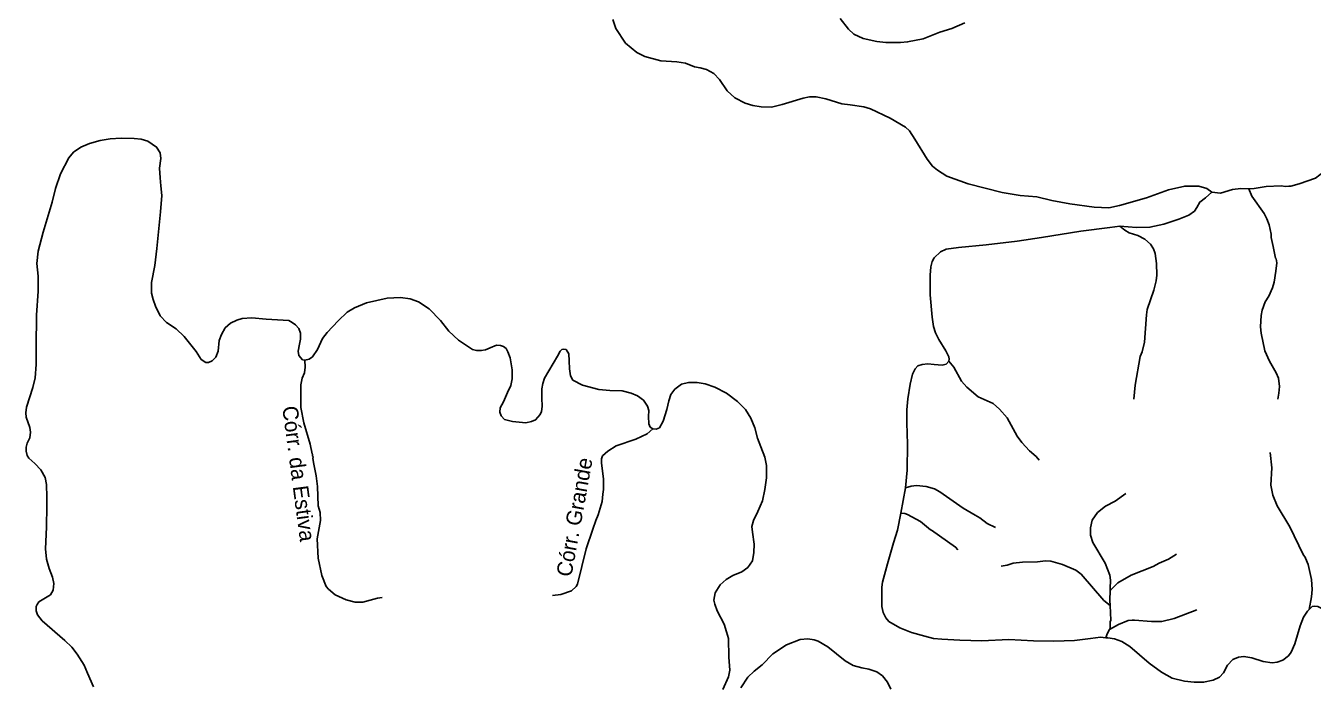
# Model space of a CAD drawing. Extents: x 396 to 422.2, y 7649.8 to 7677.6.
# Drawn here: x 402.44 to 409.11, y 7655.45 to 7658.86 of the extents above; entities that cross this region are included whole.
import ezdxf
from ezdxf.enums import TextEntityAlignment as Align

# ---------------------------------------------------------------- set-up
doc = ezdxf.new("R2010")
doc.units = 0
doc.header["$LTSCALE"] = 0.032
doc.layers.add('2', color=7, linetype='Continuous', lineweight=25)
doc.layers.add('7', color=7, linetype='Continuous', lineweight=25)
doc.layers.add('61', color=7, linetype='Continuous')

msp = doc.modelspace()

# ---------------------------------------------------------------- linework, layer by layer
at = {"layer": '2'}
for points in [[(408.5913, 7658.0004), (408.5664, 7658.0192), (408.5251, 7658.0301), (408.4514, 7658.031), (408.3678, 7658.0124), (408.2537, 7657.9701), (408.1131, 7657.9298), (408.0571, 7657.9189), (407.9814, 7657.9219), (407.8555, 7657.9396), (407.7621, 7657.9573), (407.6834, 7657.975), (407.5979, 7657.9819), (407.5035, 7657.9986), (407.3285, 7658.0428), (407.2164, 7658.0822), (407.1692, 7658.1136), (407.1426, 7658.1343), (407.1151, 7658.1707), (407.0512, 7658.2749), (407.0226, 7658.3182), (407.002, 7658.3368), (406.9224, 7658.384), (406.8211, 7658.4322), (406.7867, 7658.4421), (406.7159, 7658.4529), (406.6726, 7658.4578), (406.589, 7658.4834), (406.5398, 7658.4932), (406.5045, 7658.4932), (406.471, 7658.4873), (406.3629, 7658.4539), (406.3078, 7658.4411), (406.2537, 7658.443), (406.2104, 7658.4489), (406.1711, 7658.4607), (406.117, 7658.4883), (406.0767, 7658.5256), (406.0384, 7658.5846), (406.0089, 7658.6151), (405.9705, 7658.6358), (405.9371, 7658.6446), (405.9076, 7658.6495), (405.8614, 7658.6692), (405.8161, 7658.6761), (405.7326, 7658.68), (405.65, 7658.7036), (405.6087, 7658.7233), (405.5507, 7658.7724), (405.5005, 7658.8491), (405.4838, 7658.8954)], [(402.7899, 7655.435), (402.7584, 7655.506), (402.741, 7655.5479), (402.7061, 7655.605), (402.677, 7655.6399), (402.642, 7655.6748), (402.5233, 7655.7772), (402.5, 7655.8075), (402.4931, 7655.8296), (402.4931, 7655.8517), (402.4977, 7655.861), (402.507, 7655.875), (402.5326, 7655.8913), (402.5664, 7655.9122), (402.5815, 7655.9367), (402.585, 7655.9704), (402.578, 7656.003), (402.5606, 7656.0484), (402.5466, 7656.0961), (402.5408, 7656.1497), (402.5466, 7656.2626), (402.5478, 7656.3732), (402.5478, 7656.4186), (402.5466, 7656.4837), (402.5385, 7656.5198), (402.5175, 7656.5594), (402.4861, 7656.5931), (402.4547, 7656.6211), (402.4453, 7656.635), (402.4407, 7656.656), (402.4407, 7656.6769), (402.4453, 7656.6979), (402.4605, 7656.7258), (402.464, 7656.7561), (402.4593, 7656.7794), (402.4407, 7656.8329), (402.4384, 7656.8562), (402.4419, 7656.8841), (402.4744, 7656.9865), (402.4872, 7657.0366), (402.4919, 7657.1064), (402.4919, 7657.1972), (402.4942, 7657.3613), (402.5035, 7657.487), (402.5035, 7657.5639), (402.4966, 7657.6302), (402.5035, 7657.6931), (402.5291, 7657.7931), (402.5757, 7657.948), (402.5932, 7658.019), (402.6188, 7658.0946), (402.6618, 7658.1772), (402.6863, 7658.2075), (402.7247, 7658.2331), (402.7689, 7658.2517), (402.8248, 7658.268), (402.8772, 7658.2762), (402.933, 7658.2797), (403.0005, 7658.2785), (403.0366, 7658.275), (403.0727, 7658.2634), (403.1169, 7658.2331), (403.1356, 7658.2029), (403.139, 7658.1749), (403.1332, 7658.1237), (403.1356, 7658.0748), (403.139, 7658.0329), (403.1437, 7657.9817), (403.1379, 7657.8979), (403.1181, 7657.7073), (403.1088, 7657.6188), (403.0917, 7657.5318), (403.0917, 7657.4759)], [(408.1152, 7657.823), (408.2006, 7657.8167), (408.2705, 7657.8177), (408.3432, 7657.8344), (408.4209, 7657.859), (408.472, 7657.8796), (408.5015, 7657.9012), (408.5143, 7657.9209), (408.5291, 7657.9484), (408.5586, 7657.9711), (408.5913, 7658.0004)], [(407.2275, 7657.1227), (407.2291, 7657.1333), (407.2282, 7657.1451), (407.2124, 7657.1766), (407.176, 7657.2355), (407.1583, 7657.27), (407.1485, 7657.3034), (407.1416, 7657.3516), (407.1308, 7657.4676), (407.1308, 7657.5699), (407.1338, 7657.6122), (407.1406, 7657.6397), (407.1515, 7657.6584), (407.1849, 7657.6898), (407.2144, 7657.7036), (407.2773, 7657.7134), (407.4209, 7657.7272), (407.5812, 7657.7459), (407.708, 7657.7646), (407.9125, 7657.797), (408.062, 7657.8167), (408.1152, 7657.823)], [(403.0917, 7657.4759), (403.0995, 7657.4433), (403.1119, 7657.4092), (403.1367, 7657.3579), (403.1693, 7657.3238), (403.219, 7657.2911)], [(403.8864, 7657.1288), (403.9084, 7657.1343), (403.9255, 7657.1452), (403.9519, 7657.184), (403.9774, 7657.2405), (404.002, 7657.2729), (404.06, 7657.3329), (404.1062, 7657.3781), (404.1436, 7657.3998), (404.2055, 7657.4253), (404.3137, 7657.4509), (404.3825, 7657.4538), (404.4336, 7657.446), (404.4759, 7657.4312), (404.532, 7657.3948), (404.59, 7657.3349), (404.6342, 7657.2798), (404.6844, 7657.2316), (404.7561, 7657.1834), (404.7778, 7657.1785), (404.8014, 7657.1785), (404.824, 7657.1825), (404.8476, 7657.1923), (404.88, 7657.2061), (404.9017, 7657.2041), (404.9174, 7657.1992), (404.9312, 7657.1884), (404.939, 7657.1726), (404.9508, 7657.1412), (404.9626, 7657.0782), (404.9617, 7657.031), (404.9548, 7656.9966), (404.9381, 7656.9612), (404.9164, 7656.913), (404.8997, 7656.8816), (404.8987, 7656.8589), (404.9046, 7656.8393), (404.9223, 7656.8206), (404.9636, 7656.8108), (405.0325, 7656.8029), (405.0629, 7656.8098), (405.0836, 7656.8196), (405.1072, 7656.8471), (405.1141, 7656.8629), (405.117, 7656.8884), (405.1151, 7656.9327), (405.116, 7656.9799), (405.121, 7657.0074), (405.1298, 7657.035), (405.1967, 7657.15), (405.2104, 7657.1756), (405.2203, 7657.1834), (405.2291, 7657.1854), (405.2419, 7657.1834), (405.2557, 7657.1618), (405.2576, 7657.1244), (405.2586, 7657.0831), (405.2645, 7657.0477), (405.2773, 7657.0251), (405.3274, 7656.9986), (405.412, 7656.9769), (405.469, 7656.972), (405.533, 7656.9691), (405.5802, 7656.9573), (405.6126, 7656.9445), (405.6431, 7656.9209), (405.6637, 7656.8894), (405.6716, 7656.8678), (405.6696, 7656.8363), (405.6716, 7656.798), (405.6775, 7656.7813), (405.6909, 7656.772)], [(403.219, 7657.2911), (403.261, 7657.2508), (403.3231, 7657.1731), (403.3479, 7657.1328), (403.3728, 7657.1172), (403.3867, 7657.1172), (403.4054, 7657.125), (403.4255, 7657.1436), (403.4364, 7657.1747), (403.4411, 7657.2306), (403.4535, 7657.2616), (403.4737, 7657.2958), (403.5001, 7657.3206), (403.5342, 7657.3362), (403.5606, 7657.3455), (403.6119, 7657.3486), (403.6849, 7657.3408), (403.8029, 7657.3346), (403.8215, 7657.3238), (403.8386, 7657.3113), (403.8557, 7657.2927), (403.8634, 7657.2679), (403.8634, 7657.2383), (403.8588, 7657.212), (403.8525, 7657.1747), (403.8557, 7657.1529), (403.8743, 7657.1312), (403.8864, 7657.1288)], [(407.0023, 7656.4674), (407.0118, 7656.5581), (407.0128, 7656.6938), (407.0089, 7656.8029), (407.0099, 7656.8707), (407.0148, 7656.9288), (407.0266, 7657.0045), (407.0384, 7657.0566), (407.0521, 7657.0841), (407.0669, 7657.0989), (407.0885, 7657.1067), (407.118, 7657.1097), (407.1515, 7657.1058), (407.1928, 7657.1028), (407.2134, 7657.1077), (407.2275, 7657.1227)], [(405.6909, 7656.772), (405.709, 7656.7714), (405.7257, 7656.7773), (405.7453, 7656.8117), (405.765, 7656.8727), (405.7739, 7656.917), (405.7857, 7656.9514), (405.8063, 7656.9779), (405.8407, 7657.0035), (405.8771, 7657.0133), (405.9214, 7657.0133), (405.9627, 7657.0055), (406.0128, 7656.9878), (406.0747, 7656.9583), (406.1308, 7656.915), (406.1731, 7656.8727), (406.1996, 7656.8275), (406.2203, 7656.7783), (406.235, 7656.7242), (406.2527, 7656.68), (406.2734, 7656.6249), (406.2822, 7656.5826), (406.2822, 7656.5187), (406.2734, 7656.4578), (406.2606, 7656.3997), (406.237, 7656.3437), (406.2144, 7656.2975), (406.2045, 7656.267), (406.2085, 7656.2375), (406.2183, 7656.1746), (406.2163, 7656.1313), (406.2095, 7656.089), (406.1839, 7656.0536), (406.1534, 7656.031), (406.1062, 7656.0123), (406.0718, 7655.9917), (406.0413, 7655.9641), (406.0158, 7655.9228), (406.0089, 7655.8835), (406.0128, 7655.8629), (406.0256, 7655.8285), (406.061, 7655.7606), (406.0747, 7655.7203), (406.0836, 7655.6859), (406.0865, 7655.5895), (406.0905, 7655.5217), (406.0836, 7655.4872), (406.0541, 7655.4214)], [(408.0422, 7655.6897), (408.0148, 7655.6918), (407.9627, 7655.6859), (407.8791, 7655.6751), (407.7719, 7655.6711), (407.6667, 7655.6731), (407.5389, 7655.681), (407.3983, 7655.6741), (407.2842, 7655.676), (407.1908, 7655.6819), (407.1485, 7655.6859), (407.1033, 7655.6977), (407.0335, 7655.7164), (406.9735, 7655.74), (406.9165, 7655.7744), (406.8997, 7655.7931), (406.886, 7655.8196), (406.8801, 7655.8511), (406.8801, 7655.9514), (406.884, 7655.9769), (406.9086, 7656.0733), (406.9401, 7656.1815), (406.9617, 7656.2473), (406.9776, 7656.3348), (407.0023, 7656.4674)], [(409.6179, 7655.872), (409.5999, 7655.8432), (409.5497, 7655.7852), (409.4976, 7655.7301), (409.4602, 7655.7065), (409.4327, 7655.6957), (409.4032, 7655.6878), (409.3668, 7655.6878), (409.3314, 7655.6967), (409.2931, 7655.7164), (409.2626, 7655.737), (409.1869, 7655.8176), (409.1594, 7655.8432), (409.1417, 7655.8511), (409.123, 7655.853), (409.1131, 7655.8511), (409.0962, 7655.8359)], [(409.0962, 7655.8359), (409.0876, 7655.8265), (409.0669, 7655.796), (409.0502, 7655.7508), (409.0227, 7655.6583), (409.004, 7655.6151), (408.9892, 7655.5954), (408.9597, 7655.5738), (408.9312, 7655.562), (408.9047, 7655.559), (408.8575, 7655.5659), (408.7985, 7655.5856), (408.7582, 7655.5925), (408.7306, 7655.5885), (408.7002, 7655.5757), (408.6736, 7655.5472), (408.653, 7655.5069), (408.6323, 7655.4853), (408.5979, 7655.4695), (408.5487, 7655.4587), (408.4996, 7655.4587), (408.4504, 7655.4636), (408.3865, 7655.4804), (408.3304, 7655.5108), (408.2665, 7655.5571), (408.1662, 7655.6436), (408.1249, 7655.6692), (408.0866, 7655.6829), (408.0531, 7655.6888), (408.0422, 7655.6897)], [(406.1485, 7655.4302), (406.1849, 7655.4853), (406.2183, 7655.5167), (406.2586, 7655.5482), (406.3137, 7655.6062), (406.3845, 7655.6534), (406.4553, 7655.68), (406.4966, 7655.6839), (406.528, 7655.679), (406.5487, 7655.6721), (406.5988, 7655.6426), (406.6903, 7655.5689), (406.7306, 7655.5462), (406.7758, 7655.5335), (406.8132, 7655.5256), (406.8535, 7655.5128), (406.883, 7655.4922), (406.9086, 7655.4597), (406.9263, 7655.4233)]]:
    msp.add_lwpolyline(points, dxfattribs=at)
at = {"layer": '7'}
for points in [[(407.3106, 7658.877), (407.243, 7658.8488), (407.1802, 7658.8285), (407.0936, 7658.7954), (407.0138, 7658.7787), (406.9763, 7658.7751), (406.9006, 7658.7761), (406.8543, 7658.7806), (406.7837, 7658.7958), (406.7342, 7658.8187), (406.707, 7658.8457), (406.6631, 7658.8994)], [(409.5566, 7658.3901), (409.5118, 7658.3631), (409.4656, 7658.3248), (409.4286, 7658.3001), (409.384, 7658.2791), (409.2962, 7658.2244), (409.1978, 7658.1248), (409.1288, 7658.0721), (409.0448, 7658.0422), (409.0021, 7658.0315), (408.9914, 7658.0306), (408.9738, 7658.029), (408.9513, 7658.0319), (408.8741, 7658.0295), (408.8109, 7658.0191), (408.7832, 7658.0178)], [(408.5913, 7658.0004), (408.6371, 7657.9953), (408.6989, 7658.0135), (408.7424, 7658.0189), (408.7832, 7658.0178)], [(408.7832, 7658.0178), (408.7999, 7657.9794), (408.8626, 7657.8896), (408.8774, 7657.8615), (408.8885, 7657.8301), (408.8998, 7657.7823), (408.9, 7657.7652), (408.9098, 7657.7174), (408.9222, 7657.6574), (408.9255, 7657.6549), (408.9286, 7657.6328), (408.9246, 7657.5898), (408.9149, 7657.5324), (408.906, 7657.5032), (408.8873, 7657.4612), (408.8687, 7657.4319), (408.8525, 7657.3878), (408.8473, 7657.3608), (408.8441, 7657.3006), (408.8473, 7657.2692), (408.8669, 7657.1773), (408.8911, 7657.1242), (408.9256, 7657.0634), (408.9374, 7657.0347), (408.9421, 7656.9913), (408.9397, 7656.9582), (408.9335, 7656.9259)], [(408.1152, 7657.823), (408.1403, 7657.8025), (408.1636, 7657.7884), (408.2071, 7657.7742), (408.2448, 7657.7561), (408.2728, 7657.7299), (408.289, 7657.7065), (408.2985, 7657.681), (408.3049, 7657.6299), (408.3066, 7657.569), (408.3032, 7657.5399), (408.2905, 7657.4909), (408.2568, 7657.392), (408.2524, 7657.364), (408.2426, 7657.2225), (408.23, 7657.1722), (408.2205, 7657.1471), (408.1946, 7656.9988), (408.187, 7656.9259)], [(404.288, 7655.8979), (404.2636, 7655.8939), (404.1874, 7655.8731), (404.1481, 7655.8731), (404.1008, 7655.8865), (404.0439, 7655.912), (404.0097, 7655.9407), (403.9974, 7655.9556), (403.9744, 7656.0113), (403.9559, 7656.1021), (403.95, 7656.202), (403.9681, 7656.298), (403.9651, 7656.3393), (403.9554, 7656.3735), (403.9522, 7656.474), (403.946, 7656.5297), (403.9336, 7656.5896), (403.9274, 7656.6196), (403.9297, 7656.6282), (403.9268, 7656.6311), (403.9267, 7656.6408), (403.9236, 7656.643), (403.914, 7656.6934), (403.882, 7656.8037), (403.8661, 7656.8824), (403.8656, 7657.0001), (403.8733, 7657.0358), (403.8852, 7657.0625), (403.8884, 7657.0921), (403.8864, 7657.1288)], [(407.2275, 7657.1227), (407.254, 7657.0921), (407.2933, 7657.019), (407.3203, 7656.9885), (407.3804, 7656.9388), (407.4568, 7656.9042), (407.4909, 7656.8745), (407.5292, 7656.829), (407.5824, 7656.7337), (407.6055, 7656.7009), (407.6452, 7656.658), (407.6799, 7656.6289), (407.6965, 7656.61)], [(405.6909, 7656.772), (405.6629, 7656.7471), (405.6028, 7656.7195), (405.5011, 7656.6841), (405.4586, 7656.6568), (405.4303, 7656.6319), (405.4249, 7656.6178), (405.4253, 7656.5959), (405.4355, 7656.5119), (405.4356, 7656.4577), (405.4332, 7656.4346), (405.4291, 7656.3963), (405.4089, 7656.3265), (405.3966, 7656.2975), (405.3813, 7656.2521), (405.3467, 7656.1497), (405.3004, 7655.9676), (405.2934, 7655.955), (405.2691, 7655.9334), (405.2145, 7655.9131), (405.1717, 7655.909)], [(408.8936, 7656.6499), (408.903, 7656.5697), (408.8976, 7656.4813), (408.9078, 7656.4289), (408.9306, 7656.374), (408.9956, 7656.2648), (409.0656, 7656.1214), (409.0771, 7656.1032), (409.0775, 7656.1022), (409.0911, 7656.0692), (409.1089, 7655.9916), (409.112, 7655.939), (409.1088, 7655.9023), (409.0962, 7655.8359)], [(407.0023, 7656.4674), (407.0321, 7656.476), (407.0589, 7656.4791), (407.1091, 7656.4728), (407.1537, 7656.4607), (407.1804, 7656.446), (407.3024, 7656.3607), (407.3641, 7656.3249), (407.3876, 7656.3113), (407.4263, 7656.2823), (407.4701, 7656.2607)], [(408.1455, 7656.4365), (408.0904, 7656.3978), (408.0408, 7656.3719), (407.9984, 7656.3386), (407.9702, 7656.2984), (407.962, 7656.2595), (407.963, 7656.2209), (407.975, 7656.183), (408.0384, 7656.076), (408.0625, 7656.0142), (408.0657, 7655.9874), (408.0648, 7655.9449), (408.0646, 7655.9358)], [(406.9776, 7656.3348), (406.9986, 7656.3332), (407.0133, 7656.3283), (407.0796, 7656.2925), (407.1328, 7656.2496), (407.1376, 7656.2463), (407.2623, 7656.1596), (407.2739, 7656.1459)], [(407.4988, 7656.0606), (407.5302, 7656.0661), (407.5618, 7656.0756), (407.6092, 7656.0812), (407.6875, 7656.083), (407.7292, 7656.0877), (407.7568, 7656.0856), (407.8169, 7656.0687), (407.8854, 7656.0389), (407.9142, 7656.0189), (408.0317, 7655.8824), (408.0643, 7655.8559)], [(408.4079, 7656.1228), (408.3678, 7656.0975), (408.318, 7656.0758), (408.2871, 7656.058), (408.1734, 7656.0139), (408.1049, 7655.9735), (408.0692, 7655.9401), (408.0646, 7655.9358)], [(408.0646, 7655.9358), (408.0634, 7655.8817), (408.0643, 7655.8559)], [(408.0643, 7655.8559), (408.0671, 7655.78), (408.0642, 7655.771), (408.0635, 7655.737), (408.061, 7655.732)], [(408.5132, 7655.8341), (408.3956, 7655.7884), (408.3318, 7655.7742), (408.2808, 7655.7744), (408.2791, 7655.7744), (408.1899, 7655.7813), (408.178, 7655.7804), (408.1582, 7655.7789), (408.1075, 7655.7576), (408.061, 7655.732)], [(408.061, 7655.732), (408.0491, 7655.7089), (408.0422, 7655.6897)]]:
    msp.add_lwpolyline(points, dxfattribs=at)

# ---------------------------------------------------------------- texts
at = {"layer": '61'}
for s, rotation, p in [('Córr. da Estiva', 277.533, (403.8154, 7656.5353)), ('Córr. Grande', 79.737, (405.3243, 7656.3084))]:
    msp.add_text(s, height=0.08, rotation=rotation, dxfattribs=at).set_placement(p, align=Align.CENTER)

doc.saveas('drawing.dxf')
